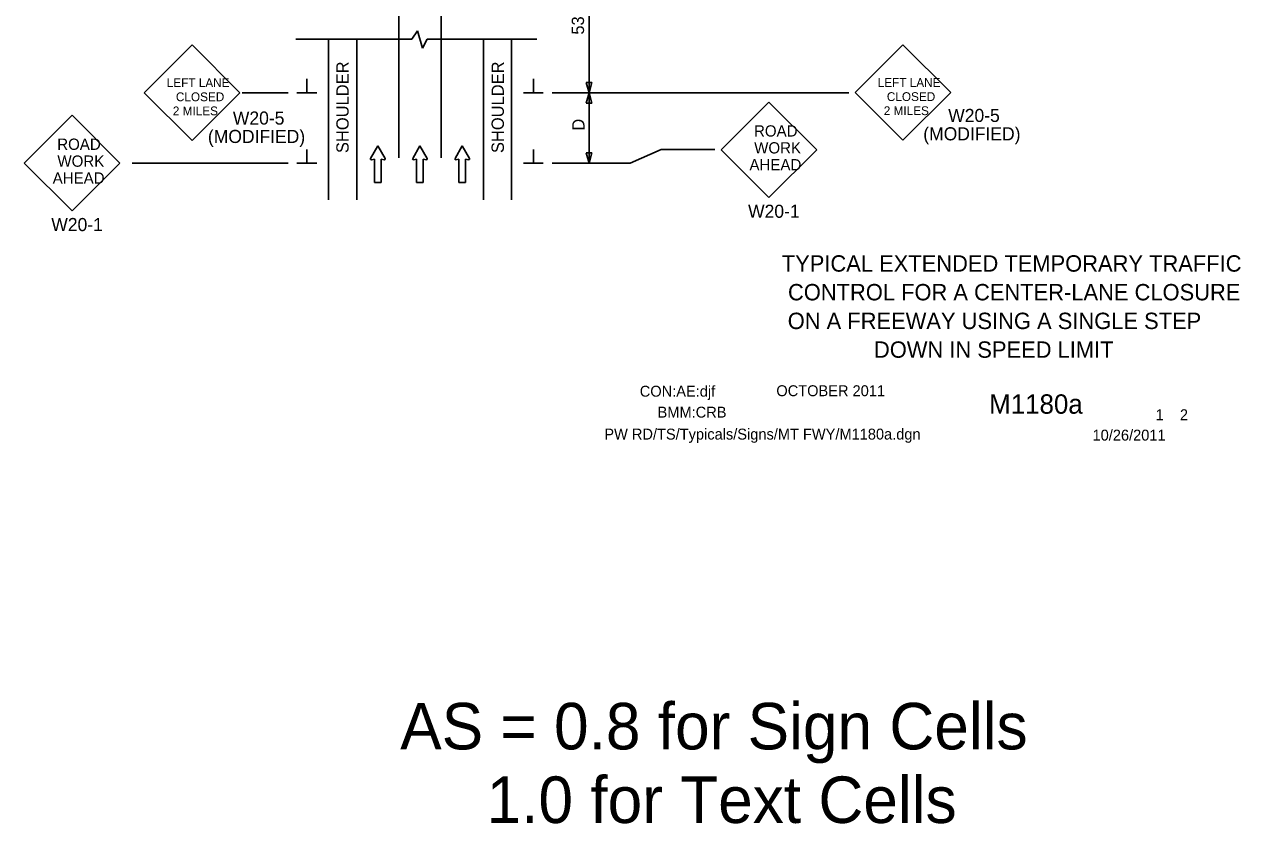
# Model space of a CAD drawing. Extents: x 16741 to 18482, y 7002 to 8333.
# Drawn here: x 16741 to 17432, y 7002 to 7456 of the extents above; entities that cross this region are included whole.
import ezdxf

# ---------------------------------------------------------------- set-up
doc = ezdxf.new("R2010")
doc.units = 0
for name, color, linetype in [('ALI_LEGAL_EX', 7, 'Continuous'), ('BORDER', 7, 'Continuous'), ('BORDER_SIGNAL_WO', 7, 'Continuous'), ('MT_SCRATCH_LEVEL_E', 7, 'Continuous'), ('PAVT_EDGE_EX', 7, 'Continuous'), ('TRAFFIC_SIGNS_PR', 7, 'Continuous'), ('TYPICAL_TEXT_DIMEN_PR', 7, 'Continuous')]:
    doc.layers.add(name, color=color, linetype=linetype)

msp = doc.modelspace()

# ---------------------------------------------------------------- linework, layer by layer
at = {"layer": 'ALI_LEGAL_EX'}
for p, q in [((16953.87, 7379.99), (16953.87, 7560.8)), ((16977.87, 7379.99), (16977.87, 7560.8))]:
    msp.add_line(p, q, dxfattribs=at)
for points in [[(16953.87, 7380.93), (16953.87, 7405.93)], [(16977.87, 7380.93), (16977.87, 7405.93)]]:
    msp.add_lwpolyline(points, dxfattribs=at)
at = {"layer": 'MT_SCRATCH_LEVEL_E'}
for p, q in [((16941.87, 7386.81), (16937.75, 7379.57)), ((16946.01, 7379.57), (16941.87, 7386.81)), ((16965.77, 7386.81), (16961.66, 7379.57)), ((16969.92, 7379.57), (16965.77, 7386.81)), ((16989.82, 7386.81), (16985.71, 7379.57)), ((16993.97, 7379.57), (16989.82, 7386.81)), ((16938.24, 7378.88), (16940.01, 7379.2)), ((16940.01, 7379.2), (16940.01, 7365.94)), ((16943.76, 7365.94), (16943.76, 7379.2)), ((16943.76, 7379.2), (16945.53, 7378.88)), ((16962.14, 7378.88), (16963.92, 7379.2)), ((16963.92, 7379.2), (16963.92, 7365.94)), ((16967.66, 7365.94), (16967.66, 7379.2)), ((16967.66, 7379.2), (16969.44, 7378.88)), ((16986.19, 7378.88), (16987.97, 7379.2)), ((16987.97, 7379.2), (16987.97, 7365.94)), ((16991.71, 7365.94), (16991.71, 7379.2)), ((16991.71, 7379.2), (16993.49, 7378.88)), ((16940.01, 7365.94), (16943.76, 7365.94)), ((16963.92, 7365.94), (16967.66, 7365.94)), ((16987.97, 7365.94), (16991.71, 7365.94))]:
    msp.add_line(p, q, dxfattribs=at)
for centre, start, end in [((16938.16, 7379.34), 150.42484, 279.96381), ((16945.6, 7379.34), 260.03619, 29.77312), ((16962.07, 7379.34), 150.42484, 279.96381), ((16969.51, 7379.34), 260.03619, 29.77312), ((16986.12, 7379.34), 150.42484, 279.96381), ((16993.56, 7379.34), 260.03619, 29.77312)]:
    msp.add_arc(centre, 0.463, start, end, dxfattribs=at)
at = {"layer": 'PAVT_EDGE_EX'}
for p, q in [((16913.87, 7447.35), (16913.87, 7356.17)), ((16929.87, 7447.35), (16929.87, 7356.17)), ((17001.87, 7447.35), (17001.87, 7356.17)), ((17017.87, 7447.35), (17017.87, 7356.17))]:
    msp.add_line(p, q, dxfattribs=at)
at = {"layer": 'TRAFFIC_SIGNS_PR'}
for p, q in [((16836.3, 7444.08), (16809.14, 7416.93)), ((16863.45, 7416.93), (16836.3, 7444.08)), ((17240.23, 7444.19), (17213.08, 7417.04)), ((17267.38, 7417.04), (17240.23, 7444.19)), ((16809.14, 7416.93), (16836.3, 7389.77)), ((16836.3, 7389.77), (16863.45, 7416.93)), ((17213.08, 7417.04), (17240.23, 7389.89)), ((17240.23, 7389.89), (17267.38, 7417.04)), ((17164.05, 7411.64), (17136.9, 7384.48)), ((17191.21, 7384.48), (17164.05, 7411.64)), ((16768.17, 7404.08), (16741.02, 7376.93)), ((16795.32, 7376.93), (16768.17, 7404.08)), ((17136.9, 7384.48), (17164.05, 7357.33)), ((17164.05, 7357.33), (17191.21, 7384.48)), ((16741.02, 7376.93), (16768.17, 7349.78)), ((16768.17, 7349.78), (16795.32, 7376.93))]:
    msp.add_line(p, q, dxfattribs=at)
at = {"layer": 'TYPICAL_TEXT_DIMEN_PR'}
for p, q in [((17061.87, 7520.21), (17061.87, 7416.94)), ((16964.47, 7452.15), (16961.21, 7447.35)), ((16967.21, 7442.21), (16964.47, 7452.15)), ((16961.21, 7447.35), (16895.27, 7447.35)), ((16969.95, 7447.35), (16967.21, 7442.21)), ((17032.29, 7447.35), (16969.95, 7447.35)), ((16901.49, 7416.94), (16901.49, 7424.72)), ((17030.24, 7416.94), (17030.24, 7424.72)), ((17061.87, 7416.94), (17060.3, 7422.8)), ((17060.3, 7422.8), (17061.87, 7422.8)), ((17061.87, 7422.8), (17063.44, 7422.8)), ((17063.44, 7422.8), (17061.87, 7416.94)), ((16864.84, 7416.94), (16890.87, 7416.94)), ((16895.87, 7416.94), (16907.12, 7416.94)), ((17035.87, 7416.94), (17024.62, 7416.94)), ((17209.44, 7416.94), (17040.87, 7416.94)), ((17060.3, 7411.07), (17061.87, 7416.94)), ((17061.87, 7416.94), (17061.87, 7376.94)), ((17061.87, 7416.94), (17063.44, 7411.07)), ((17061.87, 7411.07), (17060.3, 7411.07)), ((17063.44, 7411.07), (17061.87, 7411.07)), ((16901.49, 7376.94), (16901.49, 7384.72)), ((17030.24, 7376.94), (17030.24, 7384.72)), ((17061.87, 7376.94), (17060.3, 7382.8)), ((17060.3, 7382.8), (17061.87, 7382.8)), ((17061.87, 7382.8), (17063.44, 7382.8)), ((17063.44, 7382.8), (17061.87, 7376.94)), ((17085.28, 7376.94), (17102.85, 7384.63)), ((17133.43, 7384.63), (17102.85, 7384.63)), ((16802.2, 7376.94), (16890.87, 7376.94)), ((16895.87, 7376.94), (16907.12, 7376.94)), ((17035.87, 7376.94), (17024.62, 7376.94)), ((17085.28, 7376.94), (17040.87, 7376.94))]:
    msp.add_line(p, q, dxfattribs=at)

# ---------------------------------------------------------------- texts
at = {"layer": 'BORDER'}
for s, p in [('TYPICAL EXTENDED TEMPORARY TRAFFIC', (17171.38, 7315.31)), ('CONTROL FOR A CENTER-LANE CLOSURE', (17174.9, 7299.01)), ('ON A FREEWAY USING A SINGLE STEP ', (17174.75, 7282.71)), ('DOWN IN SPEED LIMIT', (17223.75, 7266.41))]:
    msp.add_text(s, height=9.3, dxfattribs=at).set_placement(p)
at = {"layer": 'BORDER_SIGNAL_WO'}
for s, height, p in [('CON:AE:djf  ', 6.2, (17090.69, 7244.31)), ('    OCTOBER 2011    ', 6.2, (17159.08, 7244.59)), ('    M1180a   ', 11, (17272.86, 7234.63)), ('BMM:CRB   ', 6.2, (17100.81, 7232.42)), (' 1    2 ', 6.2, (17381.45, 7230.95)), ('PW RD/TS/Typicals/Signs/MT FWY/M1180a.dgn      ', 6.2, (17070.55, 7219.96)), ('10/26/2011    ', 6.2, (17347.93, 7219.38)), ('AS = 0.8 for Sign Cells', 26.4241, (16954.57, 7044.01)), ('     1.0 for Text Cells', 26.4241, (16954.57, 7002.22))]:
    msp.add_text(s, height=height, dxfattribs=at).set_placement(p)
at = {"layer": 'TRAFFIC_SIGNS_PR'}
for s, height, p in [('LEFT LANE', 5, (16821.93, 7420.09)), ('LEFT LANE', 5, (17225.86, 7420.19)), ('CLOSED', 5, (16827.13, 7412.09)), ('CLOSED', 5, (17231.07, 7412.2)), ('2 MILES', 5, (16825.38, 7404.09)), ('2 MILES', 5, (17229.32, 7404.2)), ('W20-5', 7.44, (16859.5, 7398.81)), ('W20-5', 7.44, (17265.93, 7400.31)), ('(MODIFIED)', 7.44, (16845.32, 7388.37)), ('ROAD', 6.4, (17155.59, 7392.02)), ('(MODIFIED)', 7.44, (17251.75, 7389.87)), ('ROAD', 6.4, (16759.71, 7384.47)), ('WORK', 6.4, (17155.7, 7382.42)), ('WORK', 6.4, (16759.82, 7374.87)), ('AHEAD', 6.4, (17153.01, 7372.82)), ('AHEAD', 6.4, (16757.13, 7365.27)), ('W20-1', 7.44, (17152.22, 7345.89)), ('W20-1', 7.44, (16756.34, 7338.34))]:
    msp.add_text(s, height=height, dxfattribs=at).set_placement(p)
at = {"layer": 'TYPICAL_TEXT_DIMEN_PR'}
for s, p in [('5300 ft', (17059.02, 7449.89)), ('SHOULDER', (16925.29, 7382.65)), ('SHOULDER', (17013.49, 7382.65)), ('D', (17059.31, 7395.36))]:
    msp.add_text(s, height=7, rotation=90, dxfattribs=at).set_placement(p)

doc.saveas('drawing.dxf')
